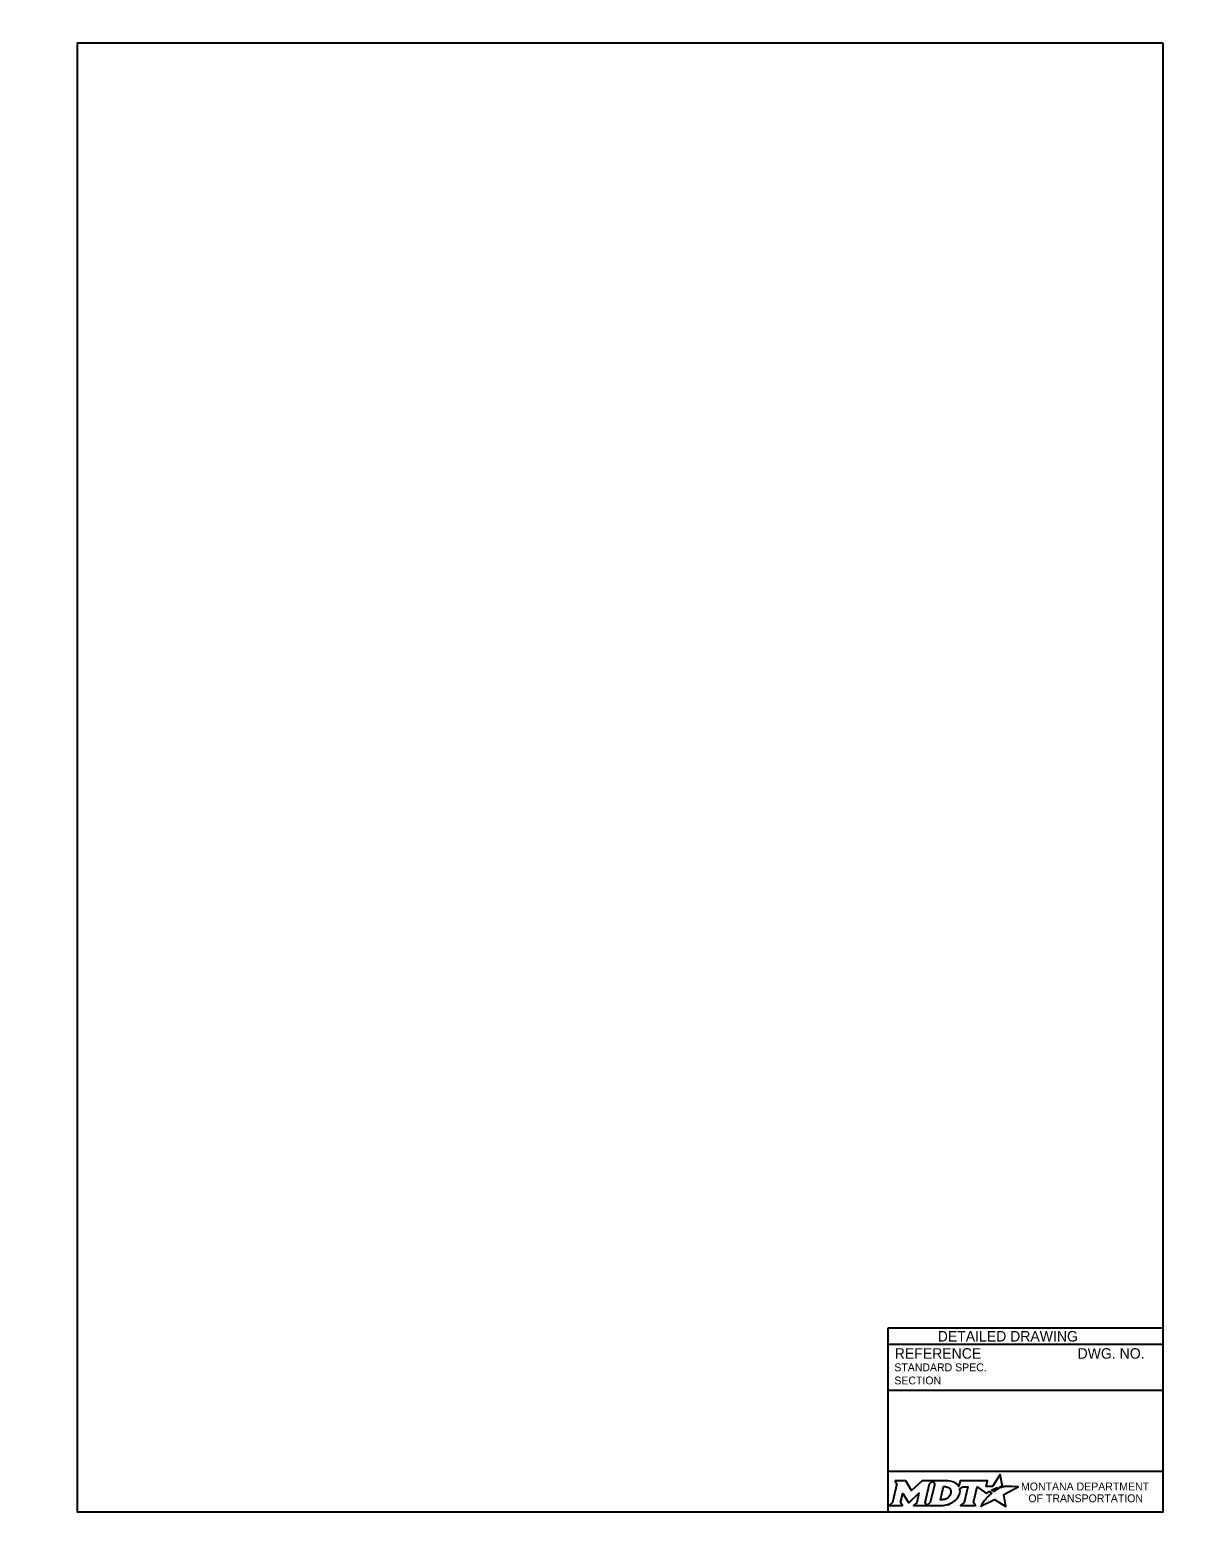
# Model space of a CAD drawing. Extents: x 49991.4 to 50021, y 49987.6 to 50011.4.
# Drawn here: x 49999.98 to 50008.76, y 49999.86 to 50011.36 of the extents above; entities that cross this region are included whole.
import ezdxf

# ---------------------------------------------------------------- set-up
doc = ezdxf.new("R2010")
doc.units = 0
doc.layers.add('Level 1', color=7, linetype='Continuous')
doc.layers.add('Level 2', color=7, linetype='Continuous')

msp = doc.modelspace()

# ---------------------------------------------------------------- linework, layer by layer
at = {"layer": 'Level 1'}
for p, q in [((50008.765, 50011.363), (50008.765, 50011.363)), ((49999.977, 49999.862), (49999.977, 49999.862))]:
    msp.add_line(p, q, dxfattribs=at)
msp.add_lwpolyline([(50008.615, 50011.263), (50000.336, 50011.263), (50000.336, 50000.062), (50008.615, 50000.062)], close=True, dxfattribs=at)
at = {"layer": 'Level 2'}
for p, q in [((50008.615, 50001.462), (50006.515, 50001.462)), ((50006.515, 50001.462), (50006.515, 50000.062)), ((50008.615, 50001.337), (50006.515, 50001.337)), ((50008.251, 50001.122), (50008.251, 50001.122)), ((50008.615, 50000.987), (50006.515, 50000.987)), ((50007.009, 50001.063), (50007.009, 50001.063)), ((50007.565, 50000.738), (50007.565, 50000.738)), ((50008.615, 50000.369), (50006.515, 50000.369))]:
    msp.add_line(p, q, dxfattribs=at)
for points in [[(50006.57, 50000.297), (50006.584, 50000.274), (50006.551, 50000.131), (50006.525, 50000.108), (50006.627, 50000.108), (50006.613, 50000.131), (50006.629, 50000.201), (50006.673, 50000.132), (50006.678, 50000.132), (50006.753, 50000.202), (50006.737, 50000.13), (50006.712, 50000.108), (50006.814, 50000.108), (50006.8, 50000.132), (50006.833, 50000.274)], [(50006.833, 50000.274), (50006.859, 50000.297), (50006.776, 50000.297), (50006.697, 50000.224), (50006.652, 50000.297), (50006.57, 50000.297)], [(50006.972, 50000.297), (50006.859, 50000.297), (50006.873, 50000.275), (50006.839, 50000.131), (50006.814, 50000.108), (50006.925, 50000.108)], [(50007.377, 50000.245), (50007.367, 50000.25), (50007.378, 50000.253), (50007.39, 50000.255), (50007.373, 50000.345), (50007.313, 50000.254), (50007.266, 50000.253), (50007.276, 50000.297), (50007.067, 50000.297), (50007.057, 50000.255), (50007.051, 50000.263)], [(50006.996, 50000.211), (50006.995, 50000.203), (50006.992, 50000.193), (50006.988, 50000.185), (50006.982, 50000.178), (50006.976, 50000.171), (50006.968, 50000.164), (50006.959, 50000.16), (50006.95, 50000.156), (50006.941, 50000.154), (50006.932, 50000.153), (50006.916, 50000.153), (50006.94, 50000.253), (50006.956, 50000.253), (50006.963, 50000.252), (50006.971, 50000.25), (50006.977, 50000.247), (50006.983, 50000.243), (50006.988, 50000.238), (50006.992, 50000.232), (50006.995, 50000.226), (50006.996, 50000.218), (50006.996, 50000.215), (50006.996, 50000.211)], [(50007.064, 50000.238), (50007.088, 50000.251), (50007.125, 50000.251), (50007.097, 50000.131), (50007.069, 50000.108), (50007.185, 50000.108), (50007.168, 50000.131), (50007.196, 50000.251), (50007.268, 50000.2), (50007.289, 50000.215), (50007.309, 50000.204)], [(50007.253, 50000.148), (50007.237, 50000.124), (50007.233, 50000.116), (50007.227, 50000.107), (50007.225, 50000.103), (50007.33, 50000.156), (50007.414, 50000.101), (50007.401, 50000.194), (50007.508, 50000.252), (50007.458, 50000.253), (50007.428, 50000.253), (50007.407, 50000.254), (50007.401, 50000.252), (50007.396, 50000.251), (50007.387, 50000.249), (50007.377, 50000.245)], [(50007.327, 50000.217), (50007.324, 50000.215), (50007.306, 50000.225), (50007.316, 50000.231), (50007.32, 50000.233), (50007.329, 50000.237), (50007.335, 50000.239), (50007.343, 50000.243), (50007.35, 50000.245), (50007.362, 50000.238), (50007.358, 50000.236), (50007.353, 50000.233), (50007.349, 50000.231), (50007.344, 50000.228), (50007.342, 50000.227), (50007.339, 50000.225), (50007.337, 50000.224), (50007.334, 50000.222), (50007.332, 50000.221), (50007.329, 50000.219), (50007.327, 50000.217)], [(50006.97, 50000.116), (50006.979, 50000.118), (50006.992, 50000.124), (50007.012, 50000.135)], [(50007.267, 50000.164), (50007.267, 50000.164)]]:
    msp.add_lwpolyline(points, dxfattribs=at)
for centre, radius, start, end in [((50006.951, 50000.236), 0.118, 300.9103, 339.1383), ((50006.995, 50000.219), 0.0709, 339.5329, 15.8582)]:
    msp.add_arc(centre, radius, start, end, dxfattribs=at)
for centre, major_axis, ratio, start_param, end_param in [((50006.97, 50000.25), (0.0834, -0.0037), 0.568097, 0.61298, 1.570796), ((50007.026, 50000.257), (0.0361, -0.0295), 0.469099, 1.225588, 1.570796), ((50007.276, 50000.174), (-0.0098, -0.0102), 0.016458, 3.141593, 6.279097), ((50007.297, 50000.194), (-0.0112, -0.0097), 0.021651, 3.157348, 6.283185), ((50006.925, 50000.257), (0, 0.148), 0.987302, 3.139398, 3.456847), ((50007.26, 50000.156), (-0.00694, -0.00806), 0.008222, 0, 3.137361)]:
    msp.add_ellipse(centre, major_axis=major_axis, ratio=ratio, start_param=start_param, end_param=end_param, dxfattribs=at)

# ---------------------------------------------------------------- texts
for s, height, p in [('DETAILED DRAWING', 0.0799, (50006.896, 50001.36)), ('REFERENCE', 0.08, (50006.568, 50001.229)), ('DWG. NO.', 0.08, (50007.962, 50001.229)), ('STANDARD SPEC.', 0.06, (50006.565, 50001.133)), ('SECTION', 0.06, (50006.565, 50001.033)), ('MONTANA DEPARTMENT', 0.06, (50007.531, 50000.224)), ('OF TRANSPORTATION', 0.06, (50007.587, 50000.134))]:
    msp.add_text(s, height=height, dxfattribs=at).set_placement(p)

doc.saveas('drawing.dxf')
